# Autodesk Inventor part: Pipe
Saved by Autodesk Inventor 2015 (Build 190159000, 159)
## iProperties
Created: 2015-04
Part Number: Pipe
Material: Generic
Document SubType Name: Modeling
Designer: Gabriel Cabellos
Density: 1 g/cm^3
Appearance: Default
Author: Gabriel Cabellos
Sending System: SolidWorks 2011
Last Author: Pets
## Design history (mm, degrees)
node "Pipe.ipt1"
node "Mirror2"
node "Base1"
